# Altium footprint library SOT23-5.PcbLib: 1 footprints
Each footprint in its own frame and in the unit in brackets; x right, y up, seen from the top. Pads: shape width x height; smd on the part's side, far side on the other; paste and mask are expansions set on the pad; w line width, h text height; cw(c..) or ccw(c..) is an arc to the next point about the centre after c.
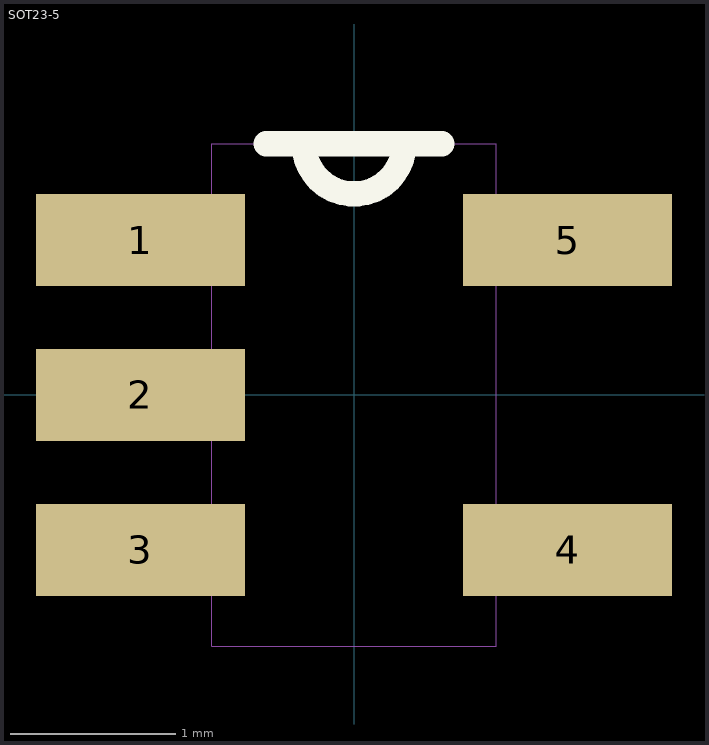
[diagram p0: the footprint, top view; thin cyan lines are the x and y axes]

## SOT23-5 [mil]
pads (5):
  rect 50x22 smd: 1(-51,37) 2(-51,0) 3(-51,-37) 4(51,-37) 5(51,37)
Top Overlay:
  lines w6: -21,60 -12,60 ; 21,60 12,60 ; -12,60 ccw(c0,60) 12,60 ; -12,60 12,60
Mechanical 13:
  lines w0: -34,-47 -59,-47 -59,-28 -34,-28 ; -34,-47 -34,-28 ; -34,-47 -34,-60 34,-60 34,-47 ; -34,-28 -34,-10 ; -34,-10 -59,-10 -59,10 -34,10 ; -34,-10 -34,10 ; -34,10 -34,28 ; -34,28 -59,28 -59,47 -34,47 ; -34,28 -34,47 ; -34,47 -34,60 -12,60 ; -12,60 ccw(c0,60) 12,60 ; -12,60 12,60 ; 12,60 34,60 34,47 ; 34,-47 59,-47 59,-28 34,-28 ; 34,-47 34,-28 ; 34,-28 34,28 ; 34,28 59,28 59,47 34,47 ; 34,28 34,47
3D body "SOT23-5.STEP": height 57.09, standoff 0, extent -54.2,-57.7 56.04,56.48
